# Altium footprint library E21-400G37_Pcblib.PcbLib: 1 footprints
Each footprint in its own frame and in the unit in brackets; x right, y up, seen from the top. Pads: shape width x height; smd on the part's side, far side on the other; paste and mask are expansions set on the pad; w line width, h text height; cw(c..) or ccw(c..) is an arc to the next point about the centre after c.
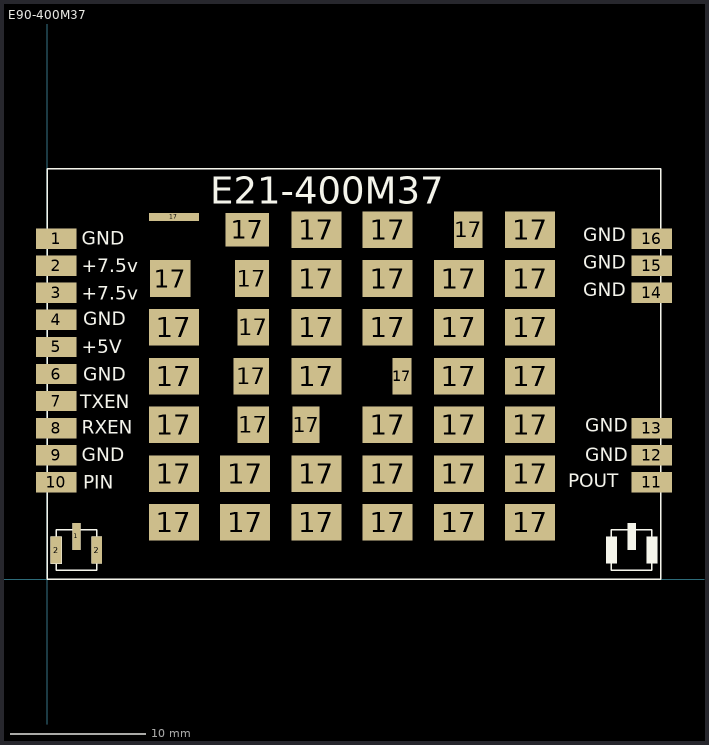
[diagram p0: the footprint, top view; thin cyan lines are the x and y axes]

## E90-400M37 [mm]
pads (61):
  rect 3x1.5 smd paste+0 mask+0.102: 1(0.65,25.15)
  rect 0.6x2 smd: 1(2.15,3.15)
  rect 3x1.5 smd paste+0: 2(0.65,23.15) 3(0.65,21.15) 4(0.65,19.15) 5(0.65,17.15) 6(0.65,15.15) 7(0.65,13.15) 8(0.65,11.15) 9(0.65,9.15) 10(0.65,7.15) 11(44.65,7.15) 12(44.65,9.15) 13(44.65,11.15) 14(44.65,21.15) 15(44.65,23.15) 16(44.65,25.15)
  rect 0.8x2 smd: 2(0.65,2.15) 2(3.65,2.15)
  rect 3x2.7 smd mask+0.102: 17(9.093,22.203)
  rect 3.7x2.7 smd mask+0.102: 17(9.343,4.195) 17(9.343,7.797) 17(9.343,11.398) 17(9.343,15) 17(9.343,18.602) 17(14.606,4.195) 17(14.606,7.797) 17(19.868,4.195) 17(19.868,7.797) 17(19.868,15) 17(19.868,18.602) 17(19.868,22.203) 17(19.868,25.805) 17(25.131,7.797) 17(25.131,11.398) 17(25.131,18.602) 17(25.131,22.203) 17(25.131,25.805) 17(25.131,4.195) 17(30.394,4.195) 17(30.394,7.797) 17(30.394,11.398) 17(30.394,15) 17(30.394,18.602) 17(30.394,22.203) 17(35.657,4.195) 17(35.657,7.797) 17(35.657,11.398) 17(35.657,15) 17(35.657,18.602) 17(35.657,22.203) 17(35.657,25.805)
  rect 3.7x0.6 smd mask+0.102: 17(9.343,26.755)
  rect 3.2x2.5 smd mask+0.102: 17(14.756,25.805)
  rect 2.6x2.7 smd mask+0.102: 17(15.056,15)
  rect 2.5x2.7 smd mask+0.102: 17(15.106,22.203)
  rect 2.3x2.7 smd mask+0.102: 17(15.206,11.398) 17(15.206,18.602)
  rect 2x2.7 smd mask+0.102: 17(19.118,11.398)
  rect 1.4x2.7 smd mask+0.102: 17(26.181,15)
  rect 2.1x2.7 smd mask+0.102: 17(31.094,25.805)
Top Layer:
  lines w0.5: 2.14,3.507 ccw(c2.277,3.507) 2.18,3.41 ; 43.14,3.14 43.16,3.16
Top Overlay:
  rectangle: 44.24,1.14 45.05,3.15
  rectangle: 42.85,2.14 43.49,4.15
  rectangle: 41.25,1.14 42.07,3.15
  rectangle: 1.85,2.14 2.46,4.15
  rectangle: 3.25,1.15 4.05,3.15
  rectangle: 0.23,1.11 1.09,3.15
  lines w0.076: 0.65,0.65 0.65,3.65 3.65,3.65 3.65,0.65 0.65,0.65
  lines w0.1: 0,0.43 0,0 ; 0,0 0.15,0 45.3,0 45.3,30.3 0,30.3 0,0.215 0,0
  lines w0.127: 0.65,0.65 0.65,3.65 3.65,3.65 3.65,0.65 0.65,0.65 ; 41.65,0.65 41.65,3.65 44.65,3.65 44.65,0.65 41.65,0.65
  text "E21-400M37" at 12.022,27.706 h2
  text "+5V" at 2.541,16.701 h1
  text "TXEN" at 2.414,12.637 h1
  text "RXEN" at 2.541,10.732 h1
  text "GND" at 2.541,8.7 h1
  text "PIN" at 2.668,6.668 h1
  text "GND" at 39.737,8.719 h1
  text "GND" at 39.737,10.878 h1
  text "GND" at 39.6,20.902 h1
  text "GND" at 39.6,22.934 h1
  text "GND" at 39.6,24.966 h1
  text "GND" at 2.668,14.669 h1
  text "GND" at 2.668,18.733 h1
  text "+7.5v" at 2.541,20.638 h1
  text "+7.5v" at 2.541,22.67 h1
  text "GND" at 2.541,24.702 h1
  text "POUT" at 38.463,6.783 h1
